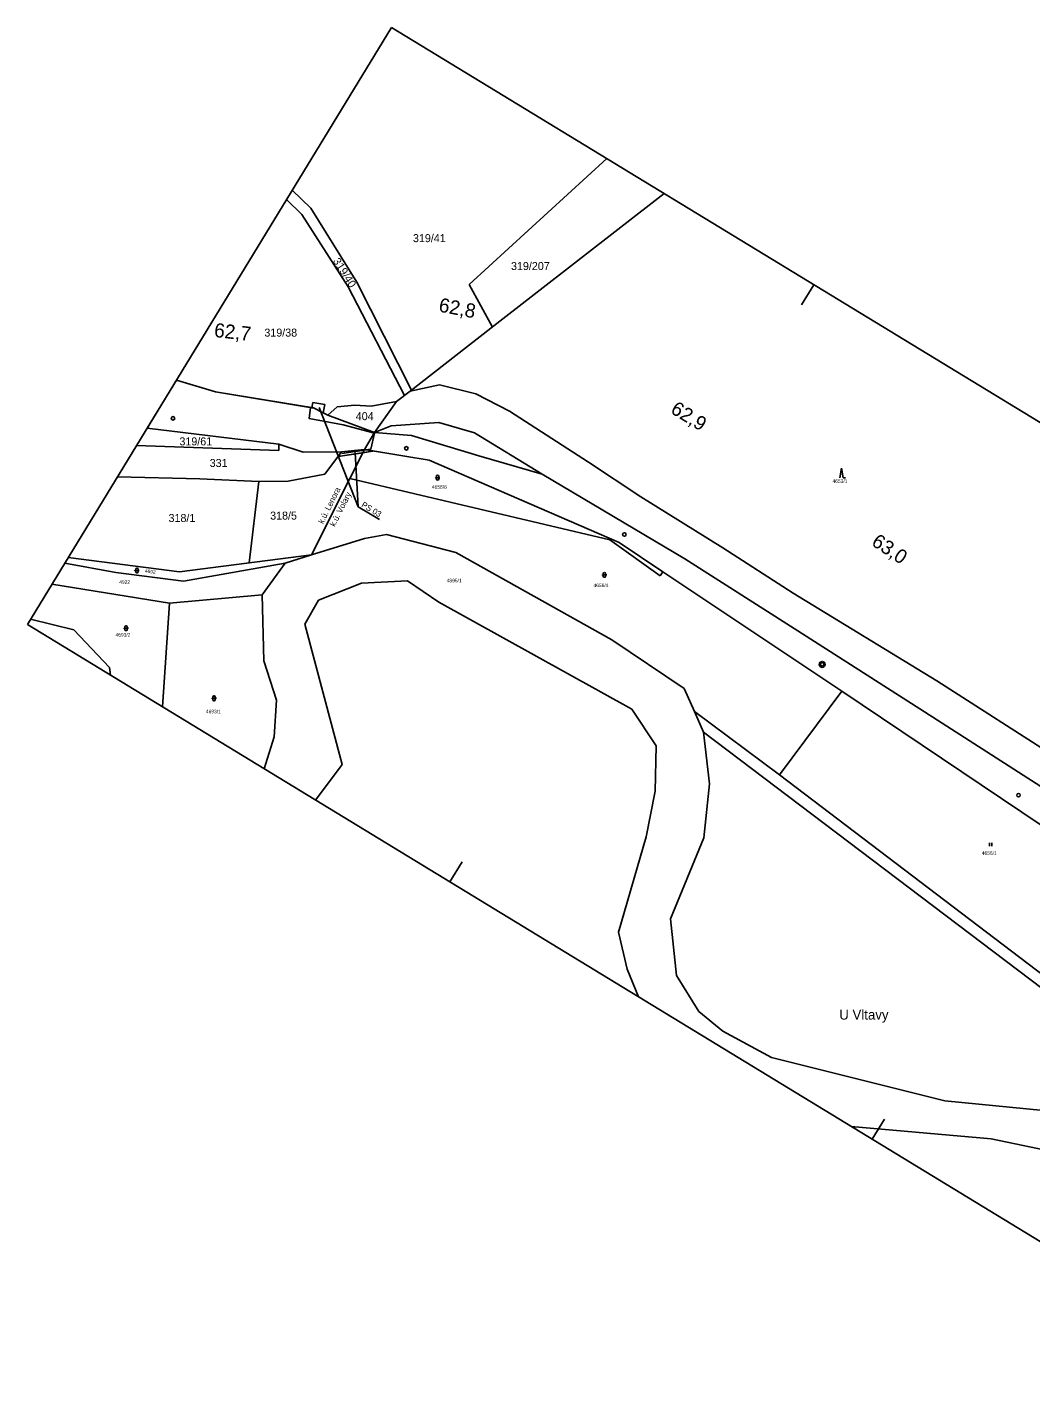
# Model space of a CAD drawing. Extents: x -804899 to -803847, y -1165742 to -1164942.
# Drawn here: x -804899 to -804473, y -1165523 to -1164942 of the extents above; entities that cross this region are included whole.
import ezdxf

# ---------------------------------------------------------------- set-up
doc = ezdxf.new("R2010")
doc.units = 0
for name, color, linetype in [('Default', 7, 'Continuous'), ('formát', 7, 'Continuous'), ('kilometráž - vrstava 7', 7, 'Continuous'), ('kn_celek - Cisla pozemkovych parcel', 7, 'Continuous'), ('kn_celek - Dalsi prvky mapy popis', 7, 'Continuous'), ('kn_celek - Hranice KU', 7, 'Continuous'), ('kn_celek - Hranice parcel', 7, 'Continuous'), ('kn_celek - názvy ku', 7, 'Continuous'), ('kn_celek - Vnitrni kresby', 7, 'Continuous'), ('kn_celek - Znacky kultur', 7, 'Continuous'), ('plochy - DZ_ostat', 7, 'Continuous'), ('plochy - SZDC', 7, 'Continuous'), ('plochy - TZ_zpf', 7, 'Continuous'), ('plochy - VB', 7, 'Continuous'), ('PSR_C2_3_trasa_Lenora - Kabelová trasa', 7, 'Continuous'), ('SOPS', 7, 'Continuous')]:
    doc.layers.add(name, color=color, linetype=linetype)

# ---------------------------------------------------------------- blocks, each defined once
blk = doc.blocks.new('306')
at = {"layer": 'Default'}
for p, q in [((-5.2, 0), (-5.2, 15)), ((4.8, 0), (4.8, 15))]:
    blk.add_line(p, q, dxfattribs=at)
blk = doc.blocks.new('316')
at = {"layer": 'Default'}
for p, q in [((-8.3, 10), (-10, 8.1)), ((-5, 10), (-8.3, 10)), ((-5, 15.5), (-5, 4.5)), ((-5, 10), (5, 10)), ((0.5, 20), (-0.5, 20)), ((-0.5, 0), (0.5, 0)), ((5, 4.5), (5, 15.5)), ((10, 10), (5, 10))]:
    blk.add_line(p, q, dxfattribs=at)
for centre, start, end in [((-0.5, 15.5), 90, 180), ((-0.5, 4.5), 180, 270), ((0.5, 15.5), 0, 90), ((0.5, 4.5), 270, 0)]:
    blk.add_arc(centre, 4.5, start, end, dxfattribs=at)
blk = doc.blocks.new('308')
at = {"layer": 'Default'}
for p, q in [((-7.5, 0.2), (0, 40.2)), ((0, 40.2), (7.5, 0.2)), ((7.5, 0.2), (17.5, 0.2))]:
    blk.add_line(p, q, dxfattribs=at)

msp = doc.modelspace()

# ---------------------------------------------------------------- linework, layer by layer
at = {"layer": 'formát'}
for p, q in [((-804743.98, -1164941.92), (-804898.57, -1165195.52)), ((-804206.05, -1165269.84), (-804743.98, -1164941.92)), ((-804564.67, -1165051.23), (-804569.87, -1165059.77)), ((-804360.64, -1165523.44), (-804898.57, -1165195.52)), ((-804714.05, -1165296.29), (-804719.26, -1165304.83)), ((-804534.74, -1165405.59), (-804539.95, -1165414.13))]:
    msp.add_line(p, q, dxfattribs=at)
at = {"layer": 'kilometráž - vrstava 7'}
for centre, radius in [((-804836.78, -1165107.96), 0.75), ((-804737.69, -1165120.69), 0.75), ((-804645.14, -1165157.27), 0.75), ((-804561.16, -1165212.47), 1.25), ((-804561.16, -1165212.47), 0.752), ((-804477.81, -1165268), 0.75)]:
    msp.add_circle(centre, radius, dxfattribs=at)
at = {"layer": 'kn_celek - Hranice KU'}
for p, q in [((-804701.79, -1165069.72), (-804628.3, -1165012.44)), ((-804736.13, -1165096.49), (-804701.79, -1165069.72)), ((-804741.92, -1165100.8), (-804736.13, -1165096.49)), ((-804751.26, -1165114.04), (-804741.92, -1165100.8)), ((-804755.48, -1165121.19), (-804751.26, -1165114.04)), ((-804761.65, -1165133.49), (-804755.48, -1165121.19)), ((-804777.95, -1165165.95), (-804761.65, -1165133.49)), ((-804881.21, -1165167.04), (-804834.02, -1165173.21)), ((-804834.02, -1165173.21), (-804777.95, -1165165.95))]:
    msp.add_line(p, q, dxfattribs=at)
at = {"layer": 'kn_celek - Hranice parcel'}
for p, q in [((-804711.07, -1165051.06), (-804652.53, -1164997.67)), ((-804786.11, -1165011.04), (-804778.25, -1165018.66)), ((-804781.99, -1165021.41), (-804788.53, -1165015.01)), ((-804701.79, -1165069.72), (-804628.3, -1165012.44)), ((-804762.33, -1165052.09), (-804781.99, -1165021.41)), ((-804778.25, -1165018.66), (-804758.75, -1165050.15)), ((-804762.33, -1165052.09), (-804738.45, -1165098.21)), ((-804758.75, -1165050.15), (-804735.46, -1165095.96)), ((-804701.13, -1165069.2), (-804711.07, -1165051.06)), ((-804736.13, -1165096.49), (-804701.79, -1165069.72)), ((-804818.68, -1165096.66), (-804835.27, -1165091.68)), ((-804777.08, -1165103.56), (-804818.68, -1165096.66)), ((-804741.92, -1165100.8), (-804736.13, -1165096.49)), ((-804736.13, -1165096.49), (-804723.61, -1165093.79)), ((-804723.61, -1165093.79), (-804708.12, -1165097.52)), ((-804708.12, -1165097.52), (-804693.95, -1165104.94)), ((-804771.09, -1165106.6), (-804777.08, -1165103.56)), ((-804767.08, -1165103.1), (-804771.09, -1165106.6)), ((-804759.5, -1165102.35), (-804767.08, -1165103.1)), ((-804752.56, -1165102.78), (-804759.5, -1165102.35)), ((-804741.92, -1165100.8), (-804752.56, -1165102.78)), ((-804751.26, -1165114.04), (-804741.92, -1165100.8)), ((-804693.95, -1165104.94), (-804660.4, -1165126.64)), ((-804771.09, -1165106.6), (-804751.26, -1165114.04)), ((-804791.88, -1165118.97), (-804847.73, -1165112.12)), ((-804755.48, -1165121.19), (-804751.26, -1165114.04)), ((-804735.44, -1165115.31), (-804751.26, -1165114.04)), ((-804735.44, -1165115.31), (-804706.98, -1165123.89)), ((-804852.21, -1165119.47), (-804791.87, -1165121.58)), ((-804781.51, -1165122.32), (-804791.88, -1165118.97)), ((-804791.87, -1165121.58), (-804791.88, -1165118.97)), ((-804781.51, -1165122.32), (-804765.27, -1165122.22)), ((-804772.23, -1165131.74), (-804765.27, -1165122.22)), ((-804765.27, -1165122.22), (-804755.48, -1165121.19)), ((-804761.65, -1165133.49), (-804755.48, -1165121.19)), ((-804738.35, -1165124.03), (-804755.48, -1165121.19)), ((-804728.07, -1165125.68), (-804738.35, -1165124.03)), ((-804728.07, -1165125.68), (-804647.39, -1165160.7)), ((-804706.98, -1165123.89), (-804680.02, -1165131.72)), ((-804660.4, -1165126.64), (-804638.1, -1165141.32)), ((-804860.31, -1165132.76), (-804825.3, -1165133.59)), ((-804825.3, -1165133.59), (-804800.3, -1165134.73)), ((-804787.89, -1165134.71), (-804772.23, -1165131.74)), ((-804777.95, -1165165.95), (-804761.65, -1165133.49)), ((-804761.65, -1165133.49), (-804651.28, -1165159.6)), ((-804680.02, -1165131.72), (-804619.47, -1165167.61)), ((-804800.3, -1165134.73), (-804804.4, -1165169.37)), ((-804800.3, -1165134.73), (-804787.89, -1165134.71)), ((-804638.1, -1165141.32), (-804603.34, -1165162.95)), ((-804755.4, -1165159), (-804746.18, -1165157.34)), ((-804746.18, -1165157.34), (-804716.61, -1165164.88)), ((-804777.95, -1165165.95), (-804755.4, -1165159)), ((-804651.28, -1165159.6), (-804629.92, -1165174.8)), ((-804647.39, -1165160.7), (-804628.74, -1165173.15)), ((-804603.34, -1165162.95), (-804573.41, -1165182.16)), ((-804881.21, -1165167.04), (-804834.02, -1165173.21)), ((-804834.02, -1165173.21), (-804777.95, -1165165.95)), ((-804789.19, -1165169.41), (-804777.95, -1165165.95)), ((-804716.61, -1165164.88), (-804650.46, -1165202.02)), ((-804619.47, -1165167.61), (-804573.03, -1165197.25)), ((-804882.71, -1165169.5), (-804861.09, -1165173.4)), ((-804861.09, -1165173.4), (-804832.28, -1165177.14)), ((-804832.28, -1165177.14), (-804789.19, -1165169.41)), ((-804798.93, -1165182.88), (-804789.19, -1165169.41)), ((-804628.74, -1165173.15), (-804629.92, -1165174.8)), ((-804628.74, -1165173.15), (-804552.85, -1165223.84)), ((-804888.13, -1165178.39), (-804838.24, -1165186.4)), ((-804775.05, -1165185.13), (-804756.66, -1165177.95)), ((-804756.66, -1165177.95), (-804737.23, -1165176.92)), ((-804737.23, -1165176.92), (-804723.84, -1165186.09)), ((-804838.24, -1165186.4), (-804841.27, -1165230.45)), ((-804838.24, -1165186.4), (-804798.93, -1165182.88)), ((-804798.22, -1165210.97), (-804798.93, -1165182.88)), ((-804780.72, -1165195.43), (-804775.05, -1165185.13)), ((-804723.84, -1165186.09), (-804641.91, -1165231.43)), ((-804573.41, -1165182.16), (-804512.48, -1165219.51)), ((-804897.23, -1165193.32), (-804878.89, -1165197.85)), ((-804878.89, -1165197.85), (-804863.7, -1165213.78)), ((-804764.95, -1165254.92), (-804780.72, -1165195.43)), ((-804573.03, -1165197.25), (-804519.76, -1165231.32)), ((-804650.46, -1165202.02), (-804619.74, -1165222.73)), ((-804863.7, -1165213.78), (-804863.24, -1165217.05)), ((-804792.79, -1165227.64), (-804798.22, -1165210.97)), ((-804512.48, -1165219.51), (-804460.87, -1165252.62)), ((-804619.74, -1165222.73), (-804615.37, -1165232.51)), ((-804552.85, -1165223.84), (-804579.26, -1165259.3)), ((-804552.85, -1165223.84), (-804418.46, -1165314.18)), ((-804793.75, -1165243.18), (-804792.79, -1165227.64)), ((-804641.91, -1165231.43), (-804631.64, -1165246.98)), ((-804615.37, -1165232.51), (-804611.48, -1165241.21)), ((-804615.37, -1165232.51), (-804579.26, -1165259.3)), ((-804519.76, -1165231.32), (-804468.27, -1165264.32)), ((-804797.98, -1165256.84), (-804793.75, -1165243.18)), ((-804611.48, -1165241.21), (-804608.95, -1165263.19)), ((-804611.48, -1165241.21), (-804462.54, -1165354.11)), ((-804631.64, -1165246.98), (-804632.08, -1165266.25)), ((-804776.22, -1165270.1), (-804764.95, -1165254.92)), ((-804579.26, -1165259.3), (-804435.81, -1165368.47)), ((-804632.08, -1165266.25), (-804635.94, -1165285.74)), ((-804608.95, -1165263.19), (-804611.41, -1165286.19)), ((-804635.94, -1165285.74), (-804647.62, -1165326.12)), ((-804611.41, -1165286.19), (-804625.54, -1165320.59)), ((-804647.62, -1165326.12), (-804643.94, -1165341.87)), ((-804625.54, -1165320.59), (-804622.94, -1165344.56)), ((-804643.94, -1165341.87), (-804639.08, -1165353.7)), ((-804622.94, -1165344.56), (-804613.5, -1165359.83)), ((-804613.5, -1165359.83), (-804603.31, -1165368.27)), ((-804603.31, -1165368.27), (-804582.68, -1165379.47)), ((-804582.68, -1165379.47), (-804509.08, -1165397.79)), ((-804509.08, -1165397.79), (-804459.92, -1165402.62)), ((-804548.78, -1165408.75), (-804489.41, -1165414.02)), ((-804489.41, -1165414.02), (-804454.38, -1165421.34))]:
    msp.add_line(p, q, dxfattribs=at)
at = {"layer": 'kn_celek - Vnitrni kresby'}
for p, q in [((-804744.11, -1165111.21), (-804723.96, -1165109.77)), ((-804723.96, -1165109.77), (-804708.7, -1165114.11)), ((-804751.26, -1165114.04), (-804744.11, -1165111.21)), ((-804708.7, -1165114.11), (-804680.02, -1165131.72))]:
    msp.add_line(p, q, dxfattribs=at)
at = {"layer": 'plochy - DZ_ostat'}
for p, q in [((-804765.27, -1165122.22), (-804766.67, -1165124.13)), ((-804766.67, -1165124.13), (-804756.18, -1165122.58)), ((-804755.48, -1165121.19), (-804765.27, -1165122.22)), ((-804755.48, -1165121.19), (-804756.18, -1165122.58)), ((-804756.18, -1165122.58), (-804755.48, -1165121.19)), ((-804751.97, -1165121.77), (-804755.48, -1165121.19))]:
    msp.add_line(p, q, dxfattribs=at)
for points in [[(-804751.97, -1165121.77), (-804752.01, -1165121.96), (-804756.18, -1165122.58)], [(-804756.18, -1165122.58), (-804752.01, -1165121.96), (-804751.97, -1165121.77)]]:
    msp.add_lwpolyline(points, dxfattribs=at)
at = {"layer": 'plochy - SZDC'}
for p, q in [((-804835.27, -1165091.68), (-804847.73, -1165112.12)), ((-804818.68, -1165096.66), (-804835.27, -1165091.68)), ((-804767.08, -1165103.1), (-804771.09, -1165106.6)), ((-804759.5, -1165102.35), (-804767.08, -1165103.1)), ((-804752.56, -1165102.78), (-804759.5, -1165102.35)), ((-804741.92, -1165100.8), (-804752.56, -1165102.78)), ((-804751.26, -1165114.04), (-804741.92, -1165100.8)), ((-804771.09, -1165106.6), (-804751.26, -1165114.04)), ((-804751.26, -1165114.04), (-804771.09, -1165106.6)), ((-804847.73, -1165112.12), (-804791.88, -1165118.97)), ((-804755.48, -1165121.19), (-804751.26, -1165114.04)), ((-804751.26, -1165114.04), (-804755.48, -1165121.19)), ((-804735.44, -1165115.31), (-804751.26, -1165114.04)), ((-804706.98, -1165123.89), (-804735.44, -1165115.31)), ((-804791.88, -1165118.97), (-804781.51, -1165122.32)), ((-804781.51, -1165122.32), (-804765.27, -1165122.22)), ((-804765.27, -1165122.22), (-804755.48, -1165121.19)), ((-804738.35, -1165124.03), (-804728.07, -1165125.68)), ((-804728.07, -1165125.68), (-804647.39, -1165160.7)), ((-804680.02, -1165131.72), (-804706.98, -1165123.89)), ((-804619.47, -1165167.61), (-804680.02, -1165131.72)), ((-804647.39, -1165160.7), (-804628.74, -1165173.15)), ((-804573.03, -1165197.25), (-804619.47, -1165167.61)), ((-804628.74, -1165173.15), (-804552.85, -1165223.84)), ((-804519.76, -1165231.32), (-804573.03, -1165197.25)), ((-804552.85, -1165223.84), (-804418.46, -1165314.18)), ((-804468.27, -1165264.32), (-804519.76, -1165231.32))]:
    msp.add_line(p, q, dxfattribs=at)
for points in [[(-804777.08, -1165103.56), (-804777.83, -1165103.43), (-804818.68, -1165096.66)], [(-804771.09, -1165106.6), (-804773.04, -1165105.61), (-804777.08, -1165103.56)], [(-804755.48, -1165121.19), (-804751.97, -1165121.77), (-804738.35, -1165124.03)]]:
    msp.add_lwpolyline(points, dxfattribs=at)
at = {"layer": 'plochy - TZ_zpf'}
for p, q in [((-804777.43, -1165101.18), (-804777.83, -1165103.43)), ((-804777.83, -1165103.43), (-804777.08, -1165103.56)), ((-804777.08, -1165103.56), (-804773.04, -1165105.61))]:
    msp.add_line(p, q, dxfattribs=at)
for points in [[(-804777.83, -1165103.43), (-804777.43, -1165101.18)], [(-804777.43, -1165101.18), (-804772.31, -1165102.11), (-804773.04, -1165105.61)], [(-804773.04, -1165105.61), (-804772.31, -1165102.11), (-804777.43, -1165101.18)]]:
    msp.add_lwpolyline(points, dxfattribs=at)
at = {"layer": 'plochy - VB'}
msp.add_lwpolyline([(-804766.67, -1165124.13), (-804765.27, -1165122.22), (-804755.48, -1165121.19), (-804751.97, -1165121.77), (-804752.01, -1165121.96)], close=True, dxfattribs=at)
at = {"layer": 'PSR_C2_3_trasa_Lenora - Kabelová trasa'}
msp.add_lwpolyline([(-804776.85, -1165103.59), (-804778.34, -1165103.41), (-804778.92, -1165108.04), (-804764.44, -1165110.74), (-804751.18, -1165114.27), (-804752.83, -1165121.07), (-804765.02, -1165122.88)], dxfattribs=at)
at = {"layer": 'SOPS'}
msp.add_line((-804774.63, -1165103.31), (-804758.13, -1165145.5), dxfattribs=at)
msp.add_lwpolyline([(-804759.42, -1165122.4), (-804758.13, -1165145.5), (-804749.12, -1165150.99)], dxfattribs=at)

# ---------------------------------------------------------------- block references
at = {"layer": 'kn_celek - Znacky kultur', "xscale": 0.1, "yscale": 0.10000000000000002}
for name, p in [('316', (-804724.45, -1165134.16)), ('308', (-804552.95, -1165133.19)), ('316', (-804852.07, -1165173.61)), ('316', (-804653.58, -1165175.48)), ('316', (-804856.68, -1165198.13)), ('316', (-804819.33, -1165227.87)), ('306', (-804489.57, -1165289.71))]:
    msp.add_blockref(name, p, dxfattribs=at)

# ---------------------------------------------------------------- texts
at = {"layer": 'kilometráž - vrstava 7'}
for s, rotation, p in [('62,8', 349.2241, (-804724.24, -1165062.57)), ('62,7', 353.55159, (-804819.5, -1165073.36)), ('62,9', 328.37907, (-804625.93, -1165105.42)), ('63,0', 326.33102, (-804540.61, -1165161.56))]:
    msp.add_text(s, height=6, rotation=rotation, dxfattribs=at).set_placement(p)
at = {"layer": 'kn_celek - Cisla pozemkovych parcel'}
for s, height, p in [('319/41', 3.4, (-804734.88, -1165033.13)), ('319/207', 3.4, (-804693.25, -1165044.98)), ('319/38', 3.4, (-804797.96, -1165073.25)), ('404', 3.4, (-804759.16, -1165108.74)), ('319/61', 3.4, (-804834.03, -1165119.45)), ('331', 3.4, (-804821.18, -1165128.61)), ('4653/1', 1.5, (-804556.78, -1165135.39)), ('4656/8', 1.5, (-804726.86, -1165137.85)), ('318/1', 3.4, (-804838.64, -1165151.98)), ('318/5', 3.4, (-804795.51, -1165150.97)), ('4922', 1.5, (-804859.6, -1165178.29)), ('4895/1', 1.5, (-804720.57, -1165177.58)), ('4656/4', 1.5, (-804658.25, -1165179.63)), ('4693/2', 1.5, (-804861.17, -1165200.67)), ('4693/1', 1.5, (-804822.79, -1165233.22)), ('4656/1', 1.5, (-804493.39, -1165293.37))]:
    msp.add_text(s, height=height, dxfattribs=at).set_placement(p)
for s, height, rotation, p in [('319/40', 3.4, 302.31031, (-804769.04, -1165041.12)), ('4692', 1.5, 352.14111, (-804848.79, -1165173.43))]:
    msp.add_text(s, height=height, rotation=rotation, dxfattribs=at).set_placement(p)
at = {"layer": 'kn_celek - Dalsi prvky mapy popis'}
msp.add_text('U Vltavy', height=4.2, dxfattribs=at).set_placement((-804553.89, -1165363.33))
at = {"layer": 'kn_celek - názvy ku'}
for s, p in [('k.ú. Lenora', (-804773.03, -1165152.99)), ('k.ú. Volary', (-804768.06, -1165154.15))]:
    msp.add_text(s, height=2.5, rotation=63.33619, dxfattribs=at).set_placement(p)
at = {"layer": 'SOPS'}
msp.add_text('PS 03', height=2.5, rotation=328.63379, dxfattribs=at).set_placement((-804757.02, -1165145.32))

doc.saveas('drawing.dxf')
